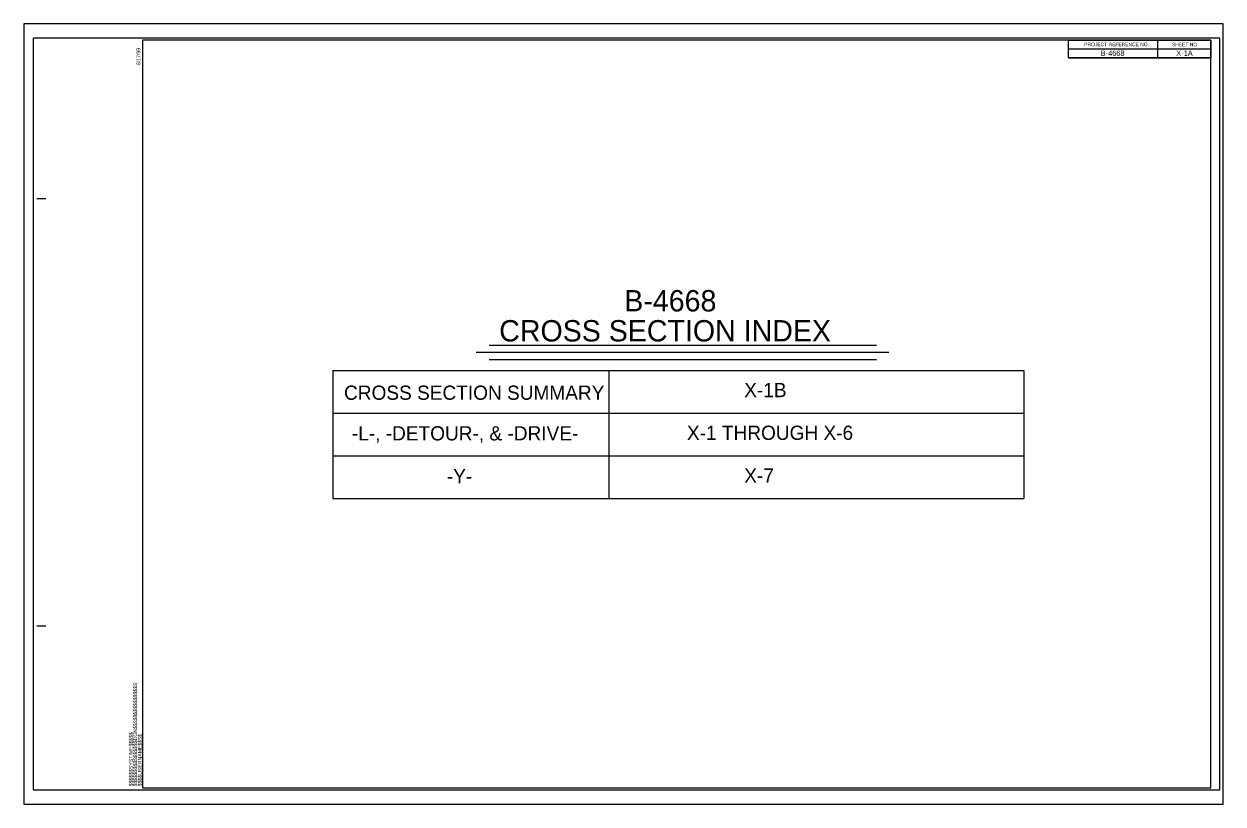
# Model space of a CAD drawing. Extents: x -158 to 684, y -32 to 516.
import ezdxf

# ---------------------------------------------------------------- set-up
doc = ezdxf.new("R2010")
doc.units = 0
for name, color, linetype in [('Old_Level_1', 7, 'Continuous'), ('Old_Level_18', 7, 'Continuous'), ('Old_Level_40', 7, 'Continuous'), ('Old_Level_41', 7, 'Continuous'), ('Old_Level_44', 7, 'Continuous'), ('Old_Level_46', 7, 'Continuous'), ('Old_Level_50', 7, 'Continuous'), ('Old_Level_51', 7, 'Continuous'), ('Old_Level_52', 7, 'Continuous')]:
    doc.layers.add(name, color=color, linetype=linetype)

msp = doc.modelspace()

# ---------------------------------------------------------------- linework, layer by layer
at = {"layer": 'Old_Level_1'}
for p, q in [((168.56, 290.37), (440.56, 290.37)), ((159.58, 285.37), (449.15, 285.37)), ((168.56, 280.37), (440.56, 280.37)), ((58.94, 272.66), (58.94, 182.66)), ((58.94, 272.66), (544.04, 272.66)), ((252.69, 272.66), (252.69, 182.66)), ((544.04, 272.66), (544.04, 182.66)), ((58.94, 242.66), (544.04, 242.66)), ((58.94, 212.66), (544.04, 212.66)), ((58.94, 182.66), (544.04, 182.66))]:
    msp.add_line(p, q, dxfattribs=at)
at = {"layer": 'Old_Level_18'}
msp.add_line((-74.68, -20.45), (-74.68, -20.45), dxfattribs=at)
msp.add_lwpolyline([(675.32, 504.55), (-74.68, 504.55), (-74.68, -20.45), (675.32, -20.45)], close=True, dxfattribs=at)
at = {"layer": 'Old_Level_40'}
for p, q in [((575.29, 498.27), (675.32, 498.27)), ((637.82, 504.52), (637.82, 492.02)), ((575.29, 492.02), (675.32, 492.02)), ((575.29, 492.02), (675.32, 492.02))]:
    msp.add_line(p, q, dxfattribs=at)
msp.add_lwpolyline([(575.29, 504.55), (675.32, 504.55), (675.32, 492.02), (575.29, 492.02)], close=True, dxfattribs=at)
at = {"layer": 'Old_Level_41'}
for p, q in [((-148.93, 393.3), (-142.68, 393.3)), ((-148.93, 93.3), (-142.68, 93.3))]:
    msp.add_line(p, q, dxfattribs=at)
at = {"layer": 'Old_Level_46'}
msp.add_line((-74.68, 504.55), (-74.68, 504.55), dxfattribs=at)
at = {"layer": 'Old_Level_50'}
for p, q in [((683.82, 515.8), (683.82, 515.8)), ((-157.93, -31.7), (-157.93, -31.7))]:
    msp.add_line(p, q, dxfattribs=at)
msp.add_lwpolyline([(-151.43, -21.7), (681.57, -21.7), (681.57, 505.8), (-151.43, 505.8)], close=True, dxfattribs=at)
at = {"layer": 'Old_Level_51'}
msp.add_lwpolyline([(-157.93, -31.7), (683.82, -31.7), (683.82, 515.8), (-157.93, 515.8)], close=True, dxfattribs=at)
at = {"layer": 'Old_Level_52'}
for p, q in [((681.57, 505.8), (681.57, 505.8)), ((-151.43, -21.7), (-151.43, -21.7))]:
    msp.add_line(p, q, dxfattribs=at)

# ---------------------------------------------------------------- texts
at = {"layer": 'Old_Level_1'}
for s, height, p in [('B-4668', 15, (263.47, 314.03)), ('CROSS SECTION INDEX', 15, (175.68, 292.95)), ('CROSS SECTION SUMMARY', 10, (66.75, 252)), ('X-1B', 10, (347.71, 253.86)), ('-L-, -DETOUR-, & -DRIVE-', 10, (72.26, 223.5)), ('X-1 THROUGH X-6', 10, (307.49, 223.86)), ('-Y-', 10, (138.93, 193.39)), ('X-7', 10, (347.71, 193.81))]:
    msp.add_text(s, height=height, dxfattribs=at).set_placement(p)
at = {"layer": 'Old_Level_41'}
for s, p in [('8/17/99', (-76.31, 486.95)), ('$$$$$$$$$$$$$$$$DGN$$$$$$$$$$$$$$$$', (-78.51, -19.27)), ('$$$$$$SYSTIME$$$$$', (-81.53, -19.27)), ('$$$$USERNAME$$$$', (-75.22, -19.27))]:
    msp.add_text(s, height=2.625, rotation=90, dxfattribs=at).set_placement(p)
at = {"layer": 'Old_Level_44'}
for s, height, p in [('PROJECT REFERENCE NO.', 2.5, (586.39, 500.2)), ('B-4668', 3.75, (597.96, 493.4)), ('SHEET NO.', 2.5, (647.97, 500.15)), ('X-1A', 3.75, (651.01, 493.42))]:
    msp.add_text(s, height=height, dxfattribs=at).set_placement(p)

doc.saveas('drawing.dxf')
